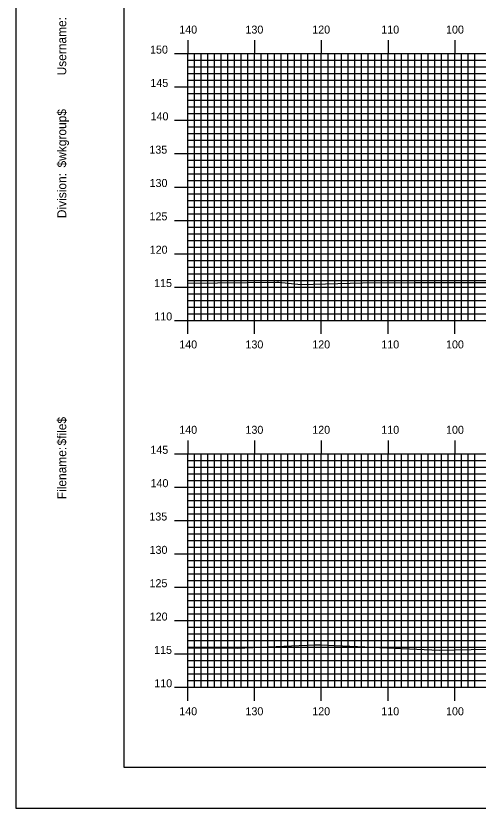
# Model space of a CAD drawing. Extents: x 1789730 to 1790074, y 442591 to 442811.
# Drawn here: x 1789730.4 to 1789799.7, y 442590.5 to 442709.3 of the extents above; entities that cross this region are included whole.
import ezdxf

# ---------------------------------------------------------------- set-up
doc = ezdxf.new("R2010")
doc.units = 0
for name, color, linetype in [('BORDER', 7, 'Continuous'), ('H_V ANNOTATION', 7, 'Continuous'), ('MAJOR', 7, 'Continuous'), ('MINOR', 7, 'Continuous'), ('PLOT BOUNDARY', 7, 'Continuous'), ('S_Roadway_Centerline', 7, 'Continuous')]:
    doc.layers.add(name, color=color, linetype=linetype)

msp = doc.modelspace()

# ---------------------------------------------------------------- linework, layer by layer
at = {"layer": 'BORDER'}
msp.add_lwpolyline([(1789746.58, 442596.67), (1790066.58, 442596.67), (1790066.58, 442806.67), (1789746.58, 442806.67)], close=True, dxfattribs=at)
at = {"layer": 'MAJOR'}
for p, q in [((1789756.18, 442705.67), (1789756.18, 442703.67)), ((1789766.18, 442705.67), (1789766.18, 442703.67)), ((1789776.18, 442705.67), (1789776.18, 442703.67)), ((1789786.18, 442705.67), (1789786.18, 442703.67)), ((1789796.18, 442705.67), (1789796.18, 442703.67)), ((1789754.18, 442703.67), (1789756.18, 442703.67)), ((1789756.18, 442703.67), (1790036.18, 442703.67)), ((1789756.18, 442663.67), (1789756.18, 442703.67)), ((1789756.18, 442663.67), (1789756.18, 442703.67)), ((1789756.18, 442703.67), (1790036.18, 442703.67)), ((1789766.18, 442663.67), (1789766.18, 442703.67)), ((1789776.18, 442663.67), (1789776.18, 442703.67)), ((1789786.18, 442663.67), (1789786.18, 442703.67)), ((1789796.18, 442663.67), (1789796.18, 442703.67)), ((1789754.18, 442698.67), (1789756.18, 442698.67)), ((1789756.18, 442698.67), (1790036.18, 442698.67)), ((1789754.18, 442693.67), (1789756.18, 442693.67)), ((1789756.18, 442693.67), (1790036.18, 442693.67)), ((1789754.18, 442688.67), (1789756.18, 442688.67)), ((1789756.18, 442688.67), (1790036.18, 442688.67)), ((1789754.18, 442683.67), (1789756.18, 442683.67)), ((1789756.18, 442683.67), (1790036.18, 442683.67)), ((1789754.18, 442678.67), (1789756.18, 442678.67)), ((1789756.18, 442678.67), (1790036.18, 442678.67)), ((1789754.18, 442673.67), (1789756.18, 442673.67)), ((1789756.18, 442673.67), (1790036.18, 442673.67)), ((1789754.18, 442668.67), (1789756.18, 442668.67)), ((1789756.18, 442668.67), (1790036.18, 442668.67)), ((1789754.18, 442663.67), (1789756.18, 442663.67)), ((1789756.18, 442663.67), (1790036.18, 442663.67)), ((1789756.18, 442663.67), (1790036.18, 442663.67)), ((1789756.18, 442661.66), (1789756.18, 442663.67)), ((1789766.18, 442661.66), (1789766.18, 442663.67)), ((1789776.18, 442661.66), (1789776.18, 442663.67)), ((1789786.18, 442661.66), (1789786.18, 442663.67)), ((1789796.18, 442661.66), (1789796.18, 442663.67)), ((1789756.18, 442645.67), (1789756.18, 442643.67)), ((1789766.18, 442645.67), (1789766.18, 442643.67)), ((1789776.18, 442645.67), (1789776.18, 442643.67)), ((1789786.18, 442645.67), (1789786.18, 442643.67)), ((1789796.18, 442645.67), (1789796.18, 442643.67)), ((1789754.18, 442643.67), (1789756.18, 442643.67)), ((1789756.18, 442643.67), (1790036.18, 442643.67)), ((1789756.18, 442608.67), (1789756.18, 442643.67)), ((1789756.18, 442608.67), (1789756.18, 442643.67)), ((1789756.18, 442643.67), (1790036.18, 442643.67)), ((1789766.18, 442608.67), (1789766.18, 442643.67)), ((1789776.18, 442608.67), (1789776.18, 442643.67)), ((1789786.18, 442608.67), (1789786.18, 442643.67)), ((1789796.18, 442608.67), (1789796.18, 442643.67)), ((1789754.18, 442638.67), (1789756.18, 442638.67)), ((1789756.18, 442638.67), (1790036.18, 442638.67)), ((1789754.18, 442633.67), (1789756.18, 442633.67)), ((1789756.18, 442633.67), (1790036.18, 442633.67)), ((1789754.18, 442628.67), (1789756.18, 442628.67)), ((1789756.18, 442628.67), (1790036.18, 442628.67)), ((1789754.18, 442623.67), (1789756.18, 442623.67)), ((1789756.18, 442623.67), (1790036.18, 442623.67)), ((1789754.18, 442618.67), (1789756.18, 442618.67)), ((1789756.18, 442618.67), (1790036.18, 442618.67)), ((1789754.18, 442613.67), (1789756.18, 442613.67)), ((1789756.18, 442613.67), (1790036.18, 442613.67)), ((1789754.18, 442608.67), (1789756.18, 442608.67)), ((1789756.18, 442608.67), (1790036.18, 442608.67)), ((1789756.18, 442608.67), (1790036.18, 442608.67)), ((1789756.18, 442606.66), (1789756.18, 442608.67)), ((1789766.18, 442606.66), (1789766.18, 442608.67)), ((1789776.18, 442606.66), (1789776.18, 442608.67)), ((1789786.18, 442606.66), (1789786.18, 442608.67)), ((1789796.18, 442606.66), (1789796.18, 442608.67))]:
    msp.add_line(p, q, dxfattribs=at)
at = {"layer": 'MINOR'}
for p, q in [((1789756.18, 442702.67), (1790036.18, 442702.67)), ((1789756.18, 442702.67), (1789758.19, 442702.67)), ((1789757.18, 442663.67), (1789757.18, 442703.67)), ((1789758.18, 442663.67), (1789758.18, 442703.67)), ((1789759.18, 442663.67), (1789759.18, 442703.67)), ((1789760.18, 442663.67), (1789760.18, 442703.67)), ((1789761.18, 442663.67), (1789761.18, 442703.67)), ((1789762.18, 442663.67), (1789762.18, 442703.67)), ((1789763.18, 442663.67), (1789763.18, 442703.67)), ((1789764.18, 442663.67), (1789764.18, 442703.67)), ((1789765.18, 442663.67), (1789765.18, 442703.67)), ((1789767.18, 442663.67), (1789767.18, 442703.67)), ((1789768.18, 442663.67), (1789768.18, 442703.67)), ((1789769.18, 442663.67), (1789769.18, 442703.67)), ((1789770.18, 442663.67), (1789770.18, 442703.67)), ((1789771.18, 442663.67), (1789771.18, 442703.67)), ((1789772.18, 442663.67), (1789772.18, 442703.67)), ((1789773.18, 442663.67), (1789773.18, 442703.67)), ((1789774.18, 442663.67), (1789774.18, 442703.67)), ((1789775.18, 442663.67), (1789775.18, 442703.67)), ((1789777.18, 442663.67), (1789777.18, 442703.67)), ((1789778.18, 442663.67), (1789778.18, 442703.67)), ((1789779.18, 442663.67), (1789779.18, 442703.67)), ((1789780.18, 442663.67), (1789780.18, 442703.67)), ((1789781.18, 442663.67), (1789781.18, 442703.67)), ((1789782.18, 442663.67), (1789782.18, 442703.67)), ((1789783.18, 442663.67), (1789783.18, 442703.67)), ((1789784.18, 442663.67), (1789784.18, 442703.67)), ((1789785.18, 442663.67), (1789785.18, 442703.67)), ((1789787.18, 442663.67), (1789787.18, 442703.67)), ((1789788.18, 442663.67), (1789788.18, 442703.67)), ((1789789.18, 442663.67), (1789789.18, 442703.67)), ((1789790.18, 442663.67), (1789790.18, 442703.67)), ((1789791.18, 442663.67), (1789791.18, 442703.67)), ((1789792.18, 442663.67), (1789792.18, 442703.67)), ((1789793.18, 442663.67), (1789793.18, 442703.67)), ((1789794.18, 442663.67), (1789794.18, 442703.67)), ((1789795.18, 442663.67), (1789795.18, 442703.67)), ((1789797.18, 442663.67), (1789797.18, 442703.67)), ((1789798.18, 442663.67), (1789798.18, 442703.67)), ((1789799.18, 442663.67), (1789799.18, 442703.67)), ((1789756.18, 442701.67), (1790036.18, 442701.67)), ((1789756.18, 442701.67), (1789758.19, 442701.67)), ((1789756.18, 442700.67), (1790036.18, 442700.67)), ((1789756.18, 442700.67), (1789758.19, 442700.67)), ((1789756.18, 442699.67), (1790036.18, 442699.67)), ((1789756.18, 442699.67), (1789758.19, 442699.67)), ((1789756.18, 442697.67), (1790036.18, 442697.67)), ((1789756.18, 442697.67), (1789758.19, 442697.67)), ((1789756.18, 442696.67), (1790036.18, 442696.67)), ((1789756.18, 442696.67), (1789758.19, 442696.67)), ((1789756.18, 442695.67), (1790036.18, 442695.67)), ((1789756.18, 442695.67), (1789758.19, 442695.67)), ((1789756.18, 442694.67), (1790036.18, 442694.67)), ((1789756.18, 442694.67), (1789758.19, 442694.67)), ((1789756.18, 442692.67), (1790036.18, 442692.67)), ((1789756.18, 442692.67), (1789758.19, 442692.67)), ((1789756.18, 442691.67), (1790036.18, 442691.67)), ((1789756.18, 442691.67), (1789758.19, 442691.67)), ((1789756.18, 442690.67), (1790036.18, 442690.67)), ((1789756.18, 442690.67), (1789758.19, 442690.67)), ((1789756.18, 442689.67), (1790036.18, 442689.67)), ((1789756.18, 442689.67), (1789758.19, 442689.67)), ((1789756.18, 442687.67), (1790036.18, 442687.67)), ((1789756.18, 442687.67), (1789758.19, 442687.67)), ((1789756.18, 442686.67), (1790036.18, 442686.67)), ((1789756.18, 442686.67), (1789758.19, 442686.67)), ((1789756.18, 442685.67), (1790036.18, 442685.67)), ((1789756.18, 442685.67), (1789758.19, 442685.67)), ((1789756.18, 442684.67), (1790036.18, 442684.67)), ((1789756.18, 442684.67), (1789758.19, 442684.67)), ((1789756.18, 442682.67), (1790036.18, 442682.67)), ((1789756.18, 442682.67), (1789758.19, 442682.67)), ((1789756.18, 442681.67), (1790036.18, 442681.67)), ((1789756.18, 442681.67), (1789758.19, 442681.67)), ((1789756.18, 442680.67), (1790036.18, 442680.67)), ((1789756.18, 442680.67), (1789758.19, 442680.67)), ((1789756.18, 442679.67), (1790036.18, 442679.67)), ((1789756.18, 442679.67), (1789758.19, 442679.67)), ((1789756.18, 442677.67), (1790036.18, 442677.67)), ((1789756.18, 442677.67), (1789758.19, 442677.67)), ((1789756.18, 442676.67), (1790036.18, 442676.67)), ((1789756.18, 442676.67), (1789758.19, 442676.67)), ((1789756.18, 442675.67), (1790036.18, 442675.67)), ((1789756.18, 442675.67), (1789758.19, 442675.67)), ((1789756.18, 442674.67), (1790036.18, 442674.67)), ((1789756.18, 442674.67), (1789758.19, 442674.67)), ((1789756.18, 442672.67), (1790036.18, 442672.67)), ((1789756.18, 442672.67), (1789758.19, 442672.67)), ((1789756.18, 442671.67), (1790036.18, 442671.67)), ((1789756.18, 442671.67), (1789758.19, 442671.67)), ((1789756.18, 442670.67), (1790036.18, 442670.67)), ((1789756.18, 442670.67), (1789758.19, 442670.67)), ((1789756.18, 442669.67), (1790036.18, 442669.67)), ((1789756.18, 442669.67), (1789758.19, 442669.67)), ((1789756.18, 442667.67), (1790036.18, 442667.67)), ((1789756.18, 442667.67), (1789758.19, 442667.67)), ((1789756.18, 442666.67), (1790036.18, 442666.67)), ((1789756.18, 442666.67), (1789758.19, 442666.67)), ((1789756.18, 442665.67), (1790036.18, 442665.67)), ((1789756.18, 442665.67), (1789758.19, 442665.67)), ((1789756.18, 442664.67), (1790036.18, 442664.67)), ((1789756.18, 442664.67), (1789758.19, 442664.67)), ((1789757.18, 442608.67), (1789757.18, 442643.67)), ((1789758.18, 442608.67), (1789758.18, 442643.67)), ((1789759.18, 442608.67), (1789759.18, 442643.67)), ((1789760.18, 442608.67), (1789760.18, 442643.67)), ((1789761.18, 442608.67), (1789761.18, 442643.67)), ((1789762.18, 442608.67), (1789762.18, 442643.67)), ((1789763.18, 442608.67), (1789763.18, 442643.67)), ((1789764.18, 442608.67), (1789764.18, 442643.67)), ((1789765.18, 442608.67), (1789765.18, 442643.67)), ((1789767.18, 442608.67), (1789767.18, 442643.67)), ((1789768.18, 442608.67), (1789768.18, 442643.67)), ((1789769.18, 442608.67), (1789769.18, 442643.67)), ((1789770.18, 442608.67), (1789770.18, 442643.67)), ((1789771.18, 442608.67), (1789771.18, 442643.67)), ((1789772.18, 442608.67), (1789772.18, 442643.67)), ((1789773.18, 442608.67), (1789773.18, 442643.67)), ((1789774.18, 442608.67), (1789774.18, 442643.67)), ((1789775.18, 442608.67), (1789775.18, 442643.67)), ((1789777.18, 442608.67), (1789777.18, 442643.67)), ((1789778.18, 442608.67), (1789778.18, 442643.67)), ((1789779.18, 442608.67), (1789779.18, 442643.67)), ((1789780.18, 442608.67), (1789780.18, 442643.67)), ((1789781.18, 442608.67), (1789781.18, 442643.67)), ((1789782.18, 442608.67), (1789782.18, 442643.67)), ((1789783.18, 442608.67), (1789783.18, 442643.67)), ((1789784.18, 442608.67), (1789784.18, 442643.67)), ((1789785.18, 442608.67), (1789785.18, 442643.67)), ((1789787.18, 442608.67), (1789787.18, 442643.67)), ((1789788.18, 442608.67), (1789788.18, 442643.67)), ((1789789.18, 442608.67), (1789789.18, 442643.67)), ((1789790.18, 442608.67), (1789790.18, 442643.67)), ((1789791.18, 442608.67), (1789791.18, 442643.67)), ((1789792.18, 442608.67), (1789792.18, 442643.67)), ((1789793.18, 442608.67), (1789793.18, 442643.67)), ((1789794.18, 442608.67), (1789794.18, 442643.67)), ((1789795.18, 442608.67), (1789795.18, 442643.67)), ((1789797.18, 442608.67), (1789797.18, 442643.67)), ((1789798.18, 442608.67), (1789798.18, 442643.67)), ((1789799.18, 442608.67), (1789799.18, 442643.67)), ((1789756.18, 442642.67), (1790036.18, 442642.67)), ((1789756.18, 442642.67), (1789758.19, 442642.67)), ((1789756.18, 442641.67), (1790036.18, 442641.67)), ((1789756.18, 442641.67), (1789758.19, 442641.67)), ((1789756.18, 442640.67), (1790036.18, 442640.67)), ((1789756.18, 442640.67), (1789758.19, 442640.67)), ((1789756.18, 442639.67), (1790036.18, 442639.67)), ((1789756.18, 442639.67), (1789758.19, 442639.67)), ((1789756.18, 442637.67), (1790036.18, 442637.67)), ((1789756.18, 442637.67), (1789758.19, 442637.67)), ((1789756.18, 442636.67), (1790036.18, 442636.67)), ((1789756.18, 442636.67), (1789758.19, 442636.67)), ((1789756.18, 442635.67), (1790036.18, 442635.67)), ((1789756.18, 442635.67), (1789758.19, 442635.67)), ((1789756.18, 442634.67), (1790036.18, 442634.67)), ((1789756.18, 442634.67), (1789758.19, 442634.67)), ((1789756.18, 442632.67), (1790036.18, 442632.67)), ((1789756.18, 442632.67), (1789758.19, 442632.67)), ((1789756.18, 442631.67), (1790036.18, 442631.67)), ((1789756.18, 442631.67), (1789758.19, 442631.67)), ((1789756.18, 442630.67), (1790036.18, 442630.67)), ((1789756.18, 442630.67), (1789758.19, 442630.67)), ((1789756.18, 442629.67), (1790036.18, 442629.67)), ((1789756.18, 442629.67), (1789758.19, 442629.67)), ((1789756.18, 442627.67), (1790036.18, 442627.67)), ((1789756.18, 442627.67), (1789758.19, 442627.67)), ((1789756.18, 442626.67), (1790036.18, 442626.67)), ((1789756.18, 442626.67), (1789758.19, 442626.67)), ((1789756.18, 442625.67), (1790036.18, 442625.67)), ((1789756.18, 442625.67), (1789758.19, 442625.67)), ((1789756.18, 442624.67), (1790036.18, 442624.67)), ((1789756.18, 442624.67), (1789758.19, 442624.67)), ((1789756.18, 442622.67), (1790036.18, 442622.67)), ((1789756.18, 442622.67), (1789758.19, 442622.67)), ((1789756.18, 442621.67), (1790036.18, 442621.67)), ((1789756.18, 442621.67), (1789758.19, 442621.67)), ((1789756.18, 442620.67), (1790036.18, 442620.67)), ((1789756.18, 442620.67), (1789758.19, 442620.67)), ((1789756.18, 442619.67), (1790036.18, 442619.67)), ((1789756.18, 442619.67), (1789758.19, 442619.67)), ((1789756.18, 442617.67), (1790036.18, 442617.67)), ((1789756.18, 442617.67), (1789758.19, 442617.67)), ((1789756.18, 442616.67), (1790036.18, 442616.67)), ((1789756.18, 442616.67), (1789758.19, 442616.67)), ((1789756.18, 442615.67), (1790036.18, 442615.67)), ((1789756.18, 442615.67), (1789758.19, 442615.67)), ((1789756.18, 442614.67), (1790036.18, 442614.67)), ((1789756.18, 442614.67), (1789758.19, 442614.67)), ((1789756.18, 442612.67), (1790036.18, 442612.67)), ((1789756.18, 442612.67), (1789758.19, 442612.67)), ((1789756.18, 442611.67), (1790036.18, 442611.67)), ((1789756.18, 442611.67), (1789758.19, 442611.67)), ((1789756.18, 442610.67), (1790036.18, 442610.67)), ((1789756.18, 442610.67), (1789758.19, 442610.67)), ((1789756.18, 442609.67), (1790036.18, 442609.67)), ((1789756.18, 442609.67), (1789758.19, 442609.67))]:
    msp.add_line(p, q, dxfattribs=at)
at = {"layer": 'PLOT BOUNDARY'}
msp.add_lwpolyline([(1789730.4, 442590.55), (1790070.4, 442590.55), (1790070.4, 442810.55), (1789730.4, 442810.55)], close=True, dxfattribs=at)
at = {"layer": 'S_Roadway_Centerline'}
for points in [[(1789756.18, 442669.24), (1789769.53, 442669.4), (1789769.82, 442669.4), (1789773.12, 442669.06), (1789782.37, 442669.28), (1789790.2, 442669.35), (1789805.09, 442669.37), (1789805.52, 442669.38), (1789806.68, 442669.4), (1789823.91, 442669.77), (1789840.83, 442670.05), (1789841.95, 442670.07), (1789843.13, 442670.1), (1789855.11, 442670.42), (1789860.76, 442670.53), (1789876.17, 442670.81)], [(1789756.18, 442614.57), (1789756.96, 442614.58), (1789763.55, 442614.53), (1789775.2, 442615.04), (1789775.62, 442615.04), (1789776, 442615.03), (1789793.85, 442614.25), (1789805.87, 442614.47), (1789810.51, 442614.56), (1789816.56, 442614.83), (1789824.94, 442615.21), (1789829.98, 442615.57), (1789837.45, 442615.65), (1789853.17, 442615.57), (1789862.01, 442615.42), (1789866.1, 442615.47), (1789877.12, 442615.72)]]:
    msp.add_lwpolyline(points, dxfattribs=at)

# ---------------------------------------------------------------- texts
at = {"layer": 'BORDER'}
for s, p in [('Username:', (1789737.95, 442700.4)), ('$wkgroup$', (1789737.95, 442686.6)), ('Division:', (1789737.95, 442679)), ('$file$', (1789737.95, 442644.92)), ('Filename:', (1789737.95, 442636.86))]:
    msp.add_text(s, height=1.339, rotation=90, dxfattribs=at).set_placement(p)
at = {"layer": 'H_V ANNOTATION'}
for s, p in [('140', (1789754.89, 442706.67)), ('130', (1789764.81, 442706.67)), ('120', (1789774.82, 442706.67)), ('110', (1789785.17, 442706.67)), ('100', (1789794.87, 442706.67)), ('150', (1789750.51, 442703.67)), ('145', (1789750.56, 442698.67)), ('140', (1789750.59, 442693.67)), ('135', (1789750.41, 442688.67)), ('130', (1789750.44, 442683.67)), ('125', (1789750.43, 442678.67)), ('120', (1789750.46, 442673.67)), ('115', (1789751.12, 442668.67)), ('110', (1789751.15, 442663.67)), ('140', (1789754.89, 442659.47)), ('130', (1789764.81, 442659.47)), ('120', (1789774.82, 442659.47)), ('110', (1789785.17, 442659.47)), ('100', (1789794.87, 442659.47)), ('140', (1789754.89, 442646.67)), ('130', (1789764.81, 442646.67)), ('120', (1789774.82, 442646.67)), ('110', (1789785.17, 442646.67)), ('100', (1789794.87, 442646.67)), ('145', (1789750.56, 442643.67)), ('140', (1789750.59, 442638.67)), ('135', (1789750.41, 442633.67)), ('130', (1789750.44, 442628.67)), ('125', (1789750.43, 442623.67)), ('120', (1789750.46, 442618.67)), ('115', (1789751.12, 442613.67)), ('110', (1789751.15, 442608.67)), ('140', (1789754.89, 442604.47)), ('130', (1789764.81, 442604.47)), ('120', (1789774.82, 442604.47)), ('110', (1789785.17, 442604.47)), ('100', (1789794.87, 442604.47))]:
    msp.add_text(s, height=1.2, dxfattribs=at).set_placement(p)
at = {"layer": 'MAJOR'}
for p in [(1789756.17, 442663.67), (1789756.17, 442608.67)]:
    msp.add_text('-', height=0.012, dxfattribs=at).set_placement(p)

doc.saveas('drawing.dxf')
